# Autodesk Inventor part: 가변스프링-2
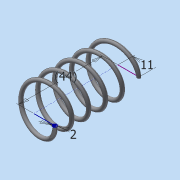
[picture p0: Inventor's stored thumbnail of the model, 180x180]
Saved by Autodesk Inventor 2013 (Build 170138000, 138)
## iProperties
Created: 2020-07
Part Number: 가변스프링-2
Material: 스테인리스강
Document SubType Name: Modeling
Designer: dgall
Density: 8.08 g/cm^3
Mass: 8.60275 g
Surface Area: 21.6357 cm^2
Volume: 1.0647 cm^3
Author: dgall
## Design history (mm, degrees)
sketch "스케치1"
  geometry: L1 (11, 0)-(0, 0); L2 (0, 0)-(0, 39.108); L3 (0, 39.108)-(11, 39.108); C1 r 1 at (11, 0)
  constraints: 6 end point, 2 horizontal, 1 centre point, 1 coincident, 1 perpendicular, 1 vertical alignment
  dimensions: "d0" = 2 diameter of C1; "d2" = 39.10829 distance of L1.end L2.end (derived); "d3" = 11 distance of L2.end L3.end
feature "코일1" pitch "d4" = 10; turns "d6" = 5; dims "d5" = 39.10829 (= d2), "d7" = 0, angle "d8" = 90 deg, angle "d9" = 90 deg, "d10" = 0, "d11" = 0
node "작업 평면2"
  node "작업 평면1"
feature "분할1"
feature "분할2"
node "솔리드1"
other parameters: "d12" = 0, "d13" = 0
